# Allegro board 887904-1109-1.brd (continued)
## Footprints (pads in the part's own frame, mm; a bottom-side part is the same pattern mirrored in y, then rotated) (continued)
PG_VG93K_F_G2D112
  round 1.778 hole 0.711: 01(20.32,1.27) 02(17.78,-1.27) 03(15.24,1.27) 04(12.7,-1.27) 05(10.16,1.27) 06(7.62,-1.27) 07(5.08,1.27) 08(2.54,-1.27) 09(0,1.27) 10(-2.54,-1.27) 11(-5.08,1.27) 12(-7.62,-1.27) 13(-10.16,1.27) 14(-12.7,-1.27) 15(-15.24,1.27) 16(-17.78,-1.27) 17(-20.32,1.27)
  rect 1.778x1.778 hole 0.711: A1(20.32,3.81) A2(17.78,1.27) A3(15.24,3.81) A4(12.7,1.27) A5(10.16,3.81) A6(7.62,1.27) A7(5.08,3.81) A8(2.54,1.27) A9(0,3.81) A10(-2.54,1.27) A11(-5.08,3.81) A12(-7.62,1.27) A13(-10.16,3.81) A14(-12.7,1.27) A15(-15.24,3.81) A16(-17.78,1.27) A17(-20.32,3.81) B1(20.32,-1.27) B2(17.78,-3.81) B3(15.24,-1.27) B4(12.7,-3.81) B5(10.16,-1.27) B6(7.62,-3.81) B7(5.08,-1.27) B8(2.54,-3.81) B9(0,-1.27) B10(-2.54,-3.81) B11(-5.08,-1.27) B12(-7.62,-3.81) B13(-10.16,-1.27) B14(-12.7,-3.81) B15(-15.24,-1.27) B16(-17.78,-3.81) B17(-20.32,-1.27)
PG_VG93K_F_G2D113
  round 1.778 hole 0.711: 01(20.32,1.27) 02(17.78,-1.27) 03(15.24,1.27) 04(12.7,-1.27) 05(10.16,1.27) 06(7.62,-1.27) 07(5.08,1.27) 08(2.54,-1.27) 09(0,1.27) 10(-2.54,-1.27) 11(-5.08,1.27) 12(-7.62,-1.27) 13(-10.16,1.27) 14(-12.7,-1.27) 15(-15.24,1.27) 16(-17.78,-1.27) 17(-20.32,1.27)
  rect 1.778x1.778 hole 0.711: A1(20.32,3.81) A2(17.78,1.27) A3(15.24,3.81) A4(12.7,1.27) A5(10.16,3.81) A6(7.62,1.27) A7(5.08,3.81) A8(2.54,1.27) A9(0,3.81) A10(-2.54,1.27) A11(-5.08,3.81) A12(-7.62,1.27) A13(-10.16,3.81) A14(-12.7,1.27) A15(-15.24,3.81) A16(-17.78,1.27) A17(-20.32,3.81) B1(20.32,-1.27) B2(17.78,-3.81) B3(15.24,-1.27) B4(12.7,-3.81) B5(10.16,-1.27) B6(7.62,-3.81) B7(5.08,-1.27) B8(2.54,-3.81) B9(0,-1.27) B10(-2.54,-3.81) B11(-5.08,-1.27) B12(-7.62,-3.81) B13(-10.16,-1.27) B14(-12.7,-3.81) B15(-15.24,-1.27) B16(-17.78,-3.81) B17(-20.32,-1.27)
PG_VG93K_F_G2D114
  round 1.778 hole 0.711: 01(20.32,1.27) 02(17.78,-1.27) 03(15.24,1.27) 04(12.7,-1.27) 05(10.16,1.27) 06(7.62,-1.27) 07(5.08,1.27) 08(2.54,-1.27) 09(0,1.27) 10(-2.54,-1.27) 11(-5.08,1.27) 12(-7.62,-1.27) 13(-10.16,1.27) 14(-12.7,-1.27) 15(-15.24,1.27) 16(-17.78,-1.27) 17(-20.32,1.27)
  rect 1.778x1.778 hole 0.711: A1(20.32,3.81) A2(17.78,1.27) A3(15.24,3.81) A4(12.7,1.27) A5(10.16,3.81) A6(7.62,1.27) A7(5.08,3.81) A8(2.54,1.27) A9(0,3.81) A10(-2.54,1.27) A11(-5.08,3.81) A12(-7.62,1.27) A13(-10.16,3.81) A14(-12.7,1.27) A15(-15.24,3.81) A16(-17.78,1.27) A17(-20.32,3.81) B1(20.32,-1.27) B2(17.78,-3.81) B3(15.24,-1.27) B4(12.7,-3.81) B5(10.16,-1.27) B6(7.62,-3.81) B7(5.08,-1.27) B8(2.54,-3.81) B9(0,-1.27) B10(-2.54,-3.81) B11(-5.08,-1.27) B12(-7.62,-3.81) B13(-10.16,-1.27) B14(-12.7,-3.81) B15(-15.24,-1.27) B16(-17.78,-3.81) B17(-20.32,-1.27)
PG_VG93K_F_G2D115
  round 1.778 hole 0.711: 01(20.32,1.27) 02(17.78,-1.27) 03(15.24,1.27) 04(12.7,-1.27) 05(10.16,1.27) 06(7.62,-1.27) 07(5.08,1.27) 08(2.54,-1.27) 09(0,1.27) 10(-2.54,-1.27) 11(-5.08,1.27) 12(-7.62,-1.27) 13(-10.16,1.27) 14(-12.7,-1.27) 15(-15.24,1.27) 16(-17.78,-1.27) 17(-20.32,1.27)
  rect 1.778x1.778 hole 0.711: A1(20.32,3.81) A2(17.78,1.27) A3(15.24,3.81) A4(12.7,1.27) A5(10.16,3.81) A6(7.62,1.27) A7(5.08,3.81) A8(2.54,1.27) A9(0,3.81) A10(-2.54,1.27) A11(-5.08,3.81) A12(-7.62,1.27) A13(-10.16,3.81) A14(-12.7,1.27) A15(-15.24,3.81) A16(-17.78,1.27) A17(-20.32,3.81) B1(20.32,-1.27) B2(17.78,-3.81) B3(15.24,-1.27) B4(12.7,-3.81) B5(10.16,-1.27) B6(7.62,-3.81) B7(5.08,-1.27) B8(2.54,-3.81) B9(0,-1.27) B10(-2.54,-3.81) B11(-5.08,-1.27) B12(-7.62,-3.81) B13(-10.16,-1.27) B14(-12.7,-3.81) B15(-15.24,-1.27) B16(-17.78,-3.81) B17(-20.32,-1.27)
PG_VG93K_F_G2D116
  round 1.778 hole 0.711: 01(20.32,1.27) 02(17.78,-1.27) 03(15.24,1.27) 04(12.7,-1.27) 05(10.16,1.27) 06(7.62,-1.27) 07(5.08,1.27) 08(2.54,-1.27) 09(0,1.27) 10(-2.54,-1.27) 11(-5.08,1.27) 12(-7.62,-1.27) 13(-10.16,1.27) 14(-12.7,-1.27) 15(-15.24,1.27) 16(-17.78,-1.27) 17(-20.32,1.27)
  rect 1.778x1.778 hole 0.711: A1(20.32,3.81) A2(17.78,1.27) A3(15.24,3.81) A4(12.7,1.27) A5(10.16,3.81) A6(7.62,1.27) A7(5.08,3.81) A8(2.54,1.27) A9(0,3.81) A10(-2.54,1.27) A11(-5.08,3.81) A12(-7.62,1.27) A13(-10.16,3.81) A14(-12.7,1.27) A15(-15.24,3.81) A16(-17.78,1.27) A17(-20.32,3.81) B1(20.32,-1.27) B2(17.78,-3.81) B3(15.24,-1.27) B4(12.7,-3.81) B5(10.16,-1.27) B6(7.62,-3.81) B7(5.08,-1.27) B8(2.54,-3.81) B9(0,-1.27) B10(-2.54,-3.81) B11(-5.08,-1.27) B12(-7.62,-3.81) B13(-10.16,-1.27) B14(-12.7,-3.81) B15(-15.24,-1.27) B16(-17.78,-3.81) B17(-20.32,-1.27)
PG_VG93K_F_G2DPS2
  round 1.778 hole 0.711: A01(20.32,2.54) A02(17.78,2.54) A03(15.24,2.54) A04(12.7,2.54) A05(10.16,2.54) A06(7.62,2.54) A07(5.08,2.54) A08(2.54,2.54) A09(0,2.54) A10(-2.54,2.54) A11(-5.08,2.54) A12(-7.62,2.54) A13(-10.16,2.54) A14(-12.7,2.54) A15(-15.24,2.54) A16(-17.78,2.54) A17(-20.32,2.54) B01(20.32,0) B02(17.78,0) B03(15.24,0) B04(12.7,0) B05(10.16,0) B06(7.62,0) B07(5.08,0) B08(2.54,0) B09(0,0) B10(-2.54,0) B11(-5.08,0) B12(-7.62,0) B13(-10.16,0) B14(-12.7,0) B15(-15.24,0) B16(-17.78,0) B17(-20.32,0) C01(20.32,-2.54) C02(17.78,-2.54) C03(15.24,-2.54) C04(12.7,-2.54) C05(10.16,-2.54) C06(7.62,-2.54) C07(5.08,-2.54) C08(2.54,-2.54) C09(0,-2.54) C10(-2.54,-2.54) C11(-5.08,-2.54) C12(-7.62,-2.54) C13(-10.16,-2.54) C14(-12.7,-2.54) C15(-15.24,-2.54) C16(-17.78,-2.54) C17(-20.32,-2.54)
PG_VG93K_F_G2UTI3
  round 1.778 hole 0.711: A01(20.32,1.27) A02(17.78,1.27) A03(15.24,1.27) A04(12.7,1.27) A05(10.16,1.27) A06(7.62,1.27) A07(5.08,1.27) A08(2.54,1.27) A09(0,1.27) A10(-2.54,1.27) A11(-5.08,1.27) A12(-7.62,1.27) A13(-10.16,1.27) A14(-12.7,1.27) A15(-15.24,1.27) A16(-17.78,1.27) A17(-20.32,1.27) B01(20.32,-1.27) B02(17.78,-1.27) B03(15.24,-1.27) B04(12.7,-1.27) B05(10.16,-1.27) B06(7.62,-1.27) B07(5.08,-1.27) B08(2.54,-1.27) B09(0,-1.27) B10(-2.54,-1.27) B11(-5.08,-1.27) B12(-7.62,-1.27) B13(-10.16,-1.27) B14(-12.7,-1.27) B15(-15.24,-1.27) B16(-17.78,-1.27) B17(-20.32,-1.27)
PG_VG93K_F_G3D120
  round 1.778 hole 0.711: 01(-20.32,-1.27) 02(-17.78,1.27) 03(-15.24,-1.27) 04(-12.7,1.27) 05(-10.16,-1.27) 06(-7.62,1.27) 07(-5.08,-1.27) 08(-2.54,1.27) 09(0,-1.27) 10(2.54,1.27) 11(5.08,-1.27) 12(7.62,1.27) 13(10.16,-1.27) 14(12.7,1.27) 15(15.24,-1.27) 16(17.78,1.27) 17(20.32,-1.27)
  rect 1.778x1.778 hole 0.711: A1(-20.32,-3.81) A2(-17.78,-1.27) A3(-15.24,-3.81) A4(-12.7,-1.27) A5(-10.16,-3.81) A6(-7.62,-1.27) A7(-5.08,-3.81) A8(-2.54,-1.27) A9(0,-3.81) A10(2.54,-1.27) A11(5.08,-3.81) A12(7.62,-1.27) A13(10.16,-3.81) A14(12.7,-1.27) A15(15.24,-3.81) A16(17.78,-1.27) A17(20.32,-3.81) B1(-20.32,1.27) B2(-17.78,3.81) B3(-15.24,1.27) B4(-12.7,3.81) B5(-10.16,1.27) B6(-7.62,3.81) B7(-5.08,1.27) B8(-2.54,3.81) B9(0,1.27) B10(2.54,3.81) B11(5.08,1.27) B12(7.62,3.81) B13(10.16,1.27) B14(12.7,3.81) B15(15.24,1.27) B16(17.78,3.81) B17(20.32,1.27)
PG_VG93K_F_G3D124
  round 1.778 hole 0.711: 01(-20.32,-1.27) 02(-17.78,1.27) 03(-15.24,-1.27) 04(-12.7,1.27) 05(-10.16,-1.27) 06(-7.62,1.27) 07(-5.08,-1.27) 08(-2.54,1.27) 09(0,-1.27) 10(2.54,1.27) 11(5.08,-1.27) 12(7.62,1.27) 13(10.16,-1.27) 14(12.7,1.27) 15(15.24,-1.27) 16(17.78,1.27) 17(20.32,-1.27)
  rect 1.778x1.778 hole 0.711: A1(-20.32,-3.81) A2(-17.78,-1.27) A3(-15.24,-3.81) A4(-12.7,-1.27) A5(-10.16,-3.81) A6(-7.62,-1.27) A7(-5.08,-3.81) A8(-2.54,-1.27) A9(0,-3.81) A10(2.54,-1.27) A11(5.08,-3.81) A12(7.62,-1.27) A13(10.16,-3.81) A14(12.7,-1.27) A15(15.24,-3.81) A16(17.78,-1.27) A17(20.32,-3.81) B1(-20.32,1.27) B2(-17.78,3.81) B3(-15.24,1.27) B4(-12.7,3.81) B5(-10.16,1.27) B6(-7.62,3.81) B7(-5.08,1.27) B8(-2.54,3.81) B9(0,1.27) B10(2.54,3.81) B11(5.08,1.27) B12(7.62,3.81) B13(10.16,1.27) B14(12.7,3.81) B15(15.24,1.27) B16(17.78,3.81) B17(20.32,1.27)
PG_VG93K_F_G3D317
  round 1.778 hole 0.711: 01(-20.32,-1.27) 02(-17.78,1.27) 03(-15.24,-1.27) 04(-12.7,1.27) 05(-10.16,-1.27) 06(-7.62,1.27) 07(-5.08,-1.27) 08(-2.54,1.27) 09(0,-1.27) 10(2.54,1.27) 11(5.08,-1.27) 12(7.62,1.27) 13(10.16,-1.27) 14(12.7,1.27) 15(15.24,-1.27) 16(17.78,1.27) 17(20.32,-1.27)
  rect 1.778x1.778 hole 0.711: A1(-20.32,-3.81) A2(-17.78,-1.27) A3(-15.24,-3.81) A4(-12.7,-1.27) A5(-10.16,-3.81) A6(-7.62,-1.27) A7(-5.08,-3.81) A8(-2.54,-1.27) A9(0,-3.81) A10(2.54,-1.27) A11(5.08,-3.81) A12(7.62,-1.27) A13(10.16,-3.81) A14(12.7,-1.27) A15(15.24,-3.81) A16(17.78,-1.27) A17(20.32,-3.81) B1(-20.32,1.27) B2(-17.78,3.81) B3(-15.24,1.27) B4(-12.7,3.81) B5(-10.16,1.27) B6(-7.62,3.81) B7(-5.08,1.27) B8(-2.54,3.81) B9(0,1.27) B10(2.54,3.81) B11(5.08,1.27) B12(7.62,3.81) B13(10.16,1.27) B14(12.7,3.81) B15(15.24,1.27) B16(17.78,3.81) B17(20.32,1.27)
PG_VG93K_F_G3D318
  round 1.778 hole 0.711: 01(-20.32,-1.27) 02(-17.78,1.27) 03(-15.24,-1.27) 04(-12.7,1.27) 05(-10.16,-1.27) 06(-7.62,1.27) 07(-5.08,-1.27) 08(-2.54,1.27) 09(0,-1.27) 10(2.54,1.27) 11(5.08,-1.27) 12(7.62,1.27) 13(10.16,-1.27) 14(12.7,1.27) 15(15.24,-1.27) 16(17.78,1.27) 17(20.32,-1.27)
  rect 1.778x1.778 hole 0.711: A1(-20.32,-3.81) A2(-17.78,-1.27) A3(-15.24,-3.81) A4(-12.7,-1.27) A5(-10.16,-3.81) A6(-7.62,-1.27) A7(-5.08,-3.81) A8(-2.54,-1.27) A9(0,-3.81) A10(2.54,-1.27) A11(5.08,-3.81) A12(7.62,-1.27) A13(10.16,-3.81) A14(12.7,-1.27) A15(15.24,-3.81) A16(17.78,-1.27) A17(20.32,-3.81) B1(-20.32,1.27) B2(-17.78,3.81) B3(-15.24,1.27) B4(-12.7,3.81) B5(-10.16,1.27) B6(-7.62,3.81) B7(-5.08,1.27) B8(-2.54,3.81) B9(0,1.27) B10(2.54,3.81) B11(5.08,1.27) B12(7.62,3.81) B13(10.16,1.27) B14(12.7,3.81) B15(15.24,1.27) B16(17.78,3.81) B17(20.32,1.27)
PG_VG93K_F_G3D321
  round 1.778 hole 0.711: 01(-20.32,-1.27) 02(-17.78,1.27) 03(-15.24,-1.27) 04(-12.7,1.27) 05(-10.16,-1.27) 06(-7.62,1.27) 07(-5.08,-1.27) 08(-2.54,1.27) 09(0,-1.27) 10(2.54,1.27) 11(5.08,-1.27) 12(7.62,1.27) 13(10.16,-1.27) 14(12.7,1.27) 15(15.24,-1.27) 16(17.78,1.27) 17(20.32,-1.27)
  rect 1.778x1.778 hole 0.711: A1(-20.32,-3.81) A2(-17.78,-1.27) A3(-15.24,-3.81) A4(-12.7,-1.27) A5(-10.16,-3.81) A6(-7.62,-1.27) A7(-5.08,-3.81) A8(-2.54,-1.27) A9(0,-3.81) A10(2.54,-1.27) A11(5.08,-3.81) A12(7.62,-1.27) A13(10.16,-3.81) A14(12.7,-1.27) A15(15.24,-3.81) A16(17.78,-1.27) A17(20.32,-3.81) B1(-20.32,1.27) B2(-17.78,3.81) B3(-15.24,1.27) B4(-12.7,3.81) B5(-10.16,1.27) B6(-7.62,3.81) B7(-5.08,1.27) B8(-2.54,3.81) B9(0,1.27) B10(2.54,3.81) B11(5.08,1.27) B12(7.62,3.81) B13(10.16,1.27) B14(12.7,3.81) B15(15.24,1.27) B16(17.78,3.81) B17(20.32,1.27)
PG_VG93K_F_G3D322
  round 1.778 hole 0.711: 01(-20.32,-1.27) 02(-17.78,1.27) 03(-15.24,-1.27) 04(-12.7,1.27) 05(-10.16,-1.27) 06(-7.62,1.27) 07(-5.08,-1.27) 08(-2.54,1.27) 09(0,-1.27) 10(2.54,1.27) 11(5.08,-1.27) 12(7.62,1.27) 13(10.16,-1.27) 14(12.7,1.27) 15(15.24,-1.27) 16(17.78,1.27) 17(20.32,-1.27)
  rect 1.778x1.778 hole 0.711: A1(-20.32,-3.81) A2(-17.78,-1.27) A3(-15.24,-3.81) A4(-12.7,-1.27) A5(-10.16,-3.81) A6(-7.62,-1.27) A7(-5.08,-3.81) A8(-2.54,-1.27) A9(0,-3.81) A10(2.54,-1.27) A11(5.08,-3.81) A12(7.62,-1.27) A13(10.16,-3.81) A14(12.7,-1.27) A15(15.24,-3.81) A16(17.78,-1.27) A17(20.32,-3.81) B1(-20.32,1.27) B2(-17.78,3.81) B3(-15.24,1.27) B4(-12.7,3.81) B5(-10.16,1.27) B6(-7.62,3.81) B7(-5.08,1.27) B8(-2.54,3.81) B9(0,1.27) B10(2.54,3.81) B11(5.08,1.27) B12(7.62,3.81) B13(10.16,1.27) B14(12.7,3.81) B15(15.24,1.27) B16(17.78,3.81) B17(20.32,1.27)
PG_VG93K_F_G3DPS3
  round 1.778 hole 0.711: A01(-20.32,-2.54) A02(-17.78,-2.54) A03(-15.24,-2.54) A04(-12.7,-2.54) A05(-10.16,-2.54) A06(-7.62,-2.54) A07(-5.08,-2.54) A08(-2.54,-2.54) A09(0,-2.54) A10(2.54,-2.54) A11(5.08,-2.54) A12(7.62,-2.54) A13(10.16,-2.54) A14(12.7,-2.54) A15(15.24,-2.54) A16(17.78,-2.54) A17(20.32,-2.54) B01(-20.32,0) B02(-17.78,0) B03(-15.24,0) B04(-12.7,0) B05(-10.16,0) B06(-7.62,0) B07(-5.08,0) B08(-2.54,0) B09(0,0) B10(2.54,0) B11(5.08,0) B12(7.62,0) B13(10.16,0) B14(12.7,0) B15(15.24,0) B16(17.78,0) B17(20.32,0) C01(-20.32,2.54) C02(-17.78,2.54) C03(-15.24,2.54) C04(-12.7,2.54) C05(-10.16,2.54) C06(-7.62,2.54) C07(-5.08,2.54) C08(-2.54,2.54) C09(0,2.54) C10(2.54,2.54) C11(5.08,2.54) C12(7.62,2.54) C13(10.16,2.54) C14(12.7,2.54) C15(15.24,2.54) C16(17.78,2.54) C17(20.32,2.54)
PG_VG93K_F_G3UTI1
  round 1.778 hole 0.711: A01(-20.32,-1.27) A02(-17.78,-1.27) A03(-15.24,-1.27) A04(-12.7,-1.27) A05(-10.16,-1.27) A06(-7.62,-1.27) A07(-5.08,-1.27) A08(-2.54,-1.27) A09(0,-1.27) A10(2.54,-1.27) A11(5.08,-1.27) A12(7.62,-1.27) A13(10.16,-1.27) A14(12.7,-1.27) A15(15.24,-1.27) A16(17.78,-1.27) A17(20.32,-1.27) B01(-20.32,1.27) B02(-17.78,1.27) B03(-15.24,1.27) B04(-12.7,1.27) B05(-10.16,1.27) B06(-7.62,1.27) B07(-5.08,1.27) B08(-2.54,1.27) B09(0,1.27) B10(2.54,1.27) B11(5.08,1.27) B12(7.62,1.27) B13(10.16,1.27) B14(12.7,1.27) B15(15.24,1.27) B16(17.78,1.27) B17(20.32,1.27)
PG_VG93K_F_G4D125
  round 1.778 hole 0.711: 01(-20.32,-1.27) 02(-17.78,1.27) 03(-15.24,-1.27) 04(-12.7,1.27) 05(-10.16,-1.27) 06(-7.62,1.27) 07(-5.08,-1.27) 08(-2.54,1.27) 09(0,-1.27) 10(2.54,1.27) 11(5.08,-1.27) 12(7.62,1.27) 13(10.16,-1.27) 14(12.7,1.27) 15(15.24,-1.27) 16(17.78,1.27) 17(20.32,-1.27)
  rect 1.778x1.778 hole 0.711: A1(-20.32,-3.81) A2(-17.78,-1.27) A3(-15.24,-3.81) A4(-12.7,-1.27) A5(-10.16,-3.81) A6(-7.62,-1.27) A7(-5.08,-3.81) A8(-2.54,-1.27) A9(0,-3.81) A10(2.54,-1.27) A11(5.08,-3.81) A12(7.62,-1.27) A13(10.16,-3.81) A14(12.7,-1.27) A15(15.24,-3.81) A16(17.78,-1.27) A17(20.32,-3.81) B1(-20.32,1.27) B2(-17.78,3.81) B3(-15.24,1.27) B4(-12.7,3.81) B5(-10.16,1.27) B6(-7.62,3.81) B7(-5.08,1.27) B8(-2.54,3.81) B9(0,1.27) B10(2.54,3.81) B11(5.08,1.27) B12(7.62,3.81) B13(10.16,1.27) B14(12.7,3.81) B15(15.24,1.27) B16(17.78,3.81) B17(20.32,1.27)
PG_VG93K_F_G4D126
  round 1.778 hole 0.711: 01(-20.32,-1.27) 02(-17.78,1.27) 03(-15.24,-1.27) 04(-12.7,1.27) 05(-10.16,-1.27) 06(-7.62,1.27) 07(-5.08,-1.27) 08(-2.54,1.27) 09(0,-1.27) 10(2.54,1.27) 11(5.08,-1.27) 12(7.62,1.27) 13(10.16,-1.27) 14(12.7,1.27) 15(15.24,-1.27) 16(17.78,1.27) 17(20.32,-1.27)
  rect 1.778x1.778 hole 0.711: A1(-20.32,-3.81) A2(-17.78,-1.27) A3(-15.24,-3.81) A4(-12.7,-1.27) A5(-10.16,-3.81) A6(-7.62,-1.27) A7(-5.08,-3.81) A8(-2.54,-1.27) A9(0,-3.81) A10(2.54,-1.27) A11(5.08,-3.81) A12(7.62,-1.27) A13(10.16,-3.81) A14(12.7,-1.27) A15(15.24,-3.81) A16(17.78,-1.27) A17(20.32,-3.81) B1(-20.32,1.27) B2(-17.78,3.81) B3(-15.24,1.27) B4(-12.7,3.81) B5(-10.16,1.27) B6(-7.62,3.81) B7(-5.08,1.27) B8(-2.54,3.81) B9(0,1.27) B10(2.54,3.81) B11(5.08,1.27) B12(7.62,3.81) B13(10.16,1.27) B14(12.7,3.81) B15(15.24,1.27) B16(17.78,3.81) B17(20.32,1.27)
PG_VG93K_F_G4D127
  round 1.778 hole 0.711: 01(-20.32,-1.27) 02(-17.78,1.27) 03(-15.24,-1.27) 04(-12.7,1.27) 05(-10.16,-1.27) 06(-7.62,1.27) 07(-5.08,-1.27) 08(-2.54,1.27) 09(0,-1.27) 10(2.54,1.27) 11(5.08,-1.27) 12(7.62,1.27) 13(10.16,-1.27) 14(12.7,1.27) 15(15.24,-1.27) 16(17.78,1.27) 17(20.32,-1.27)
  rect 1.778x1.778 hole 0.711: A1(-20.32,-3.81) A2(-17.78,-1.27) A3(-15.24,-3.81) A4(-12.7,-1.27) A5(-10.16,-3.81) A6(-7.62,-1.27) A7(-5.08,-3.81) A8(-2.54,-1.27) A9(0,-3.81) A10(2.54,-1.27) A11(5.08,-3.81) A12(7.62,-1.27) A13(10.16,-3.81) A14(12.7,-1.27) A15(15.24,-3.81) A16(17.78,-1.27) A17(20.32,-3.81) B1(-20.32,1.27) B2(-17.78,3.81) B3(-15.24,1.27) B4(-12.7,3.81) B5(-10.16,1.27) B6(-7.62,3.81) B7(-5.08,1.27) B8(-2.54,3.81) B9(0,1.27) B10(2.54,3.81) B11(5.08,1.27) B12(7.62,3.81) B13(10.16,1.27) B14(12.7,3.81) B15(15.24,1.27) B16(17.78,3.81) B17(20.32,1.27)
PG_VG93K_F_G4D128
  round 1.778 hole 0.711: 01(-20.32,-1.27) 02(-17.78,1.27) 03(-15.24,-1.27) 04(-12.7,1.27) 05(-10.16,-1.27) 06(-7.62,1.27) 07(-5.08,-1.27) 08(-2.54,1.27) 09(0,-1.27) 10(2.54,1.27) 11(5.08,-1.27) 12(7.62,1.27) 13(10.16,-1.27) 14(12.7,1.27) 15(15.24,-1.27) 16(17.78,1.27) 17(20.32,-1.27)
  rect 1.778x1.778 hole 0.711: A1(-20.32,-3.81) A2(-17.78,-1.27) A3(-15.24,-3.81) A4(-12.7,-1.27) A5(-10.16,-3.81) A6(-7.62,-1.27) A7(-5.08,-3.81) A8(-2.54,-1.27) A9(0,-3.81) A10(2.54,-1.27) A11(5.08,-3.81) A12(7.62,-1.27) A13(10.16,-3.81) A14(12.7,-1.27) A15(15.24,-3.81) A16(17.78,-1.27) A17(20.32,-3.81) B1(-20.32,1.27) B2(-17.78,3.81) B3(-15.24,1.27) B4(-12.7,3.81) B5(-10.16,1.27) B6(-7.62,3.81) B7(-5.08,1.27) B8(-2.54,3.81) B9(0,1.27) B10(2.54,3.81) B11(5.08,1.27) B12(7.62,3.81) B13(10.16,1.27) B14(12.7,3.81) B15(15.24,1.27) B16(17.78,3.81) B17(20.32,1.27)
PG_VG93K_F_G4D129
  round 1.778 hole 0.711: 01(-20.32,-1.27) 02(-17.78,1.27) 03(-15.24,-1.27) 04(-12.7,1.27) 05(-10.16,-1.27) 06(-7.62,1.27) 07(-5.08,-1.27) 08(-2.54,1.27) 09(0,-1.27) 10(2.54,1.27) 11(5.08,-1.27) 12(7.62,1.27) 13(10.16,-1.27) 14(12.7,1.27) 15(15.24,-1.27) 16(17.78,1.27) 17(20.32,-1.27)
  rect 1.778x1.778 hole 0.711: A1(-20.32,-3.81) A2(-17.78,-1.27) A3(-15.24,-3.81) A4(-12.7,-1.27) A5(-10.16,-3.81) A6(-7.62,-1.27) A7(-5.08,-3.81) A8(-2.54,-1.27) A9(0,-3.81) A10(2.54,-1.27) A11(5.08,-3.81) A12(7.62,-1.27) A13(10.16,-3.81) A14(12.7,-1.27) A15(15.24,-3.81) A16(17.78,-1.27) A17(20.32,-3.81) B1(-20.32,1.27) B2(-17.78,3.81) B3(-15.24,1.27) B4(-12.7,3.81) B5(-10.16,1.27) B6(-7.62,3.81) B7(-5.08,1.27) B8(-2.54,3.81) B9(0,1.27) B10(2.54,3.81) B11(5.08,1.27) B12(7.62,3.81) B13(10.16,1.27) B14(12.7,3.81) B15(15.24,1.27) B16(17.78,3.81) B17(20.32,1.27)
PG_VG93K_F_G4D130
  round 1.778 hole 0.711: 01(-20.32,-1.27) 02(-17.78,1.27) 03(-15.24,-1.27) 04(-12.7,1.27) 05(-10.16,-1.27) 06(-7.62,1.27) 07(-5.08,-1.27) 08(-2.54,1.27) 09(0,-1.27) 10(2.54,1.27) 11(5.08,-1.27) 12(7.62,1.27) 13(10.16,-1.27) 14(12.7,1.27) 15(15.24,-1.27) 16(17.78,1.27) 17(20.32,-1.27)
  rect 1.778x1.778 hole 0.711: A1(-20.32,-3.81) A2(-17.78,-1.27) A3(-15.24,-3.81) A4(-12.7,-1.27) A5(-10.16,-3.81) A6(-7.62,-1.27) A7(-5.08,-3.81) A8(-2.54,-1.27) A9(0,-3.81) A10(2.54,-1.27) A11(5.08,-3.81) A12(7.62,-1.27) A13(10.16,-3.81) A14(12.7,-1.27) A15(15.24,-3.81) A16(17.78,-1.27) A17(20.32,-3.81) B1(-20.32,1.27) B2(-17.78,3.81) B3(-15.24,1.27) B4(-12.7,3.81) B5(-10.16,1.27) B6(-7.62,3.81) B7(-5.08,1.27) B8(-2.54,3.81) B9(0,1.27) B10(2.54,3.81) B11(5.08,1.27) B12(7.62,3.81) B13(10.16,1.27) B14(12.7,3.81) B15(15.24,1.27) B16(17.78,3.81) B17(20.32,1.27)
PG_VG93K_F_G4D131
  round 1.778 hole 0.711: 01(-20.32,-1.27) 02(-17.78,1.27) 03(-15.24,-1.27) 04(-12.7,1.27) 05(-10.16,-1.27) 06(-7.62,1.27) 07(-5.08,-1.27) 08(-2.54,1.27) 09(0,-1.27) 10(2.54,1.27) 11(5.08,-1.27) 12(7.62,1.27) 13(10.16,-1.27) 14(12.7,1.27) 15(15.24,-1.27) 16(17.78,1.27) 17(20.32,-1.27)
  rect 1.778x1.778 hole 0.711: A1(-20.32,-3.81) A2(-17.78,-1.27) A3(-15.24,-3.81) A4(-12.7,-1.27) A5(-10.16,-3.81) A6(-7.62,-1.27) A7(-5.08,-3.81) A8(-2.54,-1.27) A9(0,-3.81) A10(2.54,-1.27) A11(5.08,-3.81) A12(7.62,-1.27) A13(10.16,-3.81) A14(12.7,-1.27) A15(15.24,-3.81) A16(17.78,-1.27) A17(20.32,-3.81) B1(-20.32,1.27) B2(-17.78,3.81) B3(-15.24,1.27) B4(-12.7,3.81) B5(-10.16,1.27) B6(-7.62,3.81) B7(-5.08,1.27) B8(-2.54,3.81) B9(0,1.27) B10(2.54,3.81) B11(5.08,1.27) B12(7.62,3.81) B13(10.16,1.27) B14(12.7,3.81) B15(15.24,1.27) B16(17.78,3.81) B17(20.32,1.27)
PG_VG93K_F_G4D132
  round 1.778 hole 0.711: 01(-20.32,-1.27) 02(-17.78,1.27) 03(-15.24,-1.27) 04(-12.7,1.27) 05(-10.16,-1.27) 06(-7.62,1.27) 07(-5.08,-1.27) 08(-2.54,1.27) 09(0,-1.27) 10(2.54,1.27) 11(5.08,-1.27) 12(7.62,1.27) 13(10.16,-1.27) 14(12.7,1.27) 15(15.24,-1.27) 16(17.78,1.27) 17(20.32,-1.27)
  rect 1.778x1.778 hole 0.711: A1(-20.32,-3.81) A2(-17.78,-1.27) A3(-15.24,-3.81) A4(-12.7,-1.27) A5(-10.16,-3.81) A6(-7.62,-1.27) A7(-5.08,-3.81) A8(-2.54,-1.27) A9(0,-3.81) A10(2.54,-1.27) A11(5.08,-3.81) A12(7.62,-1.27) A13(10.16,-3.81) A14(12.7,-1.27) A15(15.24,-3.81) A16(17.78,-1.27) A17(20.32,-3.81) B1(-20.32,1.27) B2(-17.78,3.81) B3(-15.24,1.27) B4(-12.7,3.81) B5(-10.16,1.27) B6(-7.62,3.81) B7(-5.08,1.27) B8(-2.54,3.81) B9(0,1.27) B10(2.54,3.81) B11(5.08,1.27) B12(7.62,3.81) B13(10.16,1.27) B14(12.7,3.81) B15(15.24,1.27) B16(17.78,3.81) B17(20.32,1.27)
PG_VG93K_F_G4DPS4
  round 1.778 hole 0.711: A01(-20.32,-2.54) A02(-17.78,-2.54) A03(-15.24,-2.54) A04(-12.7,-2.54) A05(-10.16,-2.54) A06(-7.62,-2.54) A07(-5.08,-2.54) A08(-2.54,-2.54) A09(0,-2.54) A10(2.54,-2.54) A11(5.08,-2.54) A12(7.62,-2.54) A13(10.16,-2.54) A14(12.7,-2.54) A15(15.24,-2.54) A16(17.78,-2.54) A17(20.32,-2.54) B01(-20.32,0) B02(-17.78,0) B03(-15.24,0) B04(-12.7,0) B05(-10.16,0) B06(-7.62,0) B07(-5.08,0) B08(-2.54,0) B09(0,0) B10(2.54,0) B11(5.08,0) B12(7.62,0) B13(10.16,0) B14(12.7,0) B15(15.24,0) B16(17.78,0) B17(20.32,0) C01(-20.32,2.54) C02(-17.78,2.54) C03(-15.24,2.54) C04(-12.7,2.54) C05(-10.16,2.54) C06(-7.62,2.54) C07(-5.08,2.54) C08(-2.54,2.54) C09(0,2.54) C10(2.54,2.54) C11(5.08,2.54) C12(7.62,2.54) C13(10.16,2.54) C14(12.7,2.54) C15(15.24,2.54) C16(17.78,2.54) C17(20.32,2.54)
PG_VG93K_F_G4UTI5
  round 1.778 hole 0.711: A01(-20.32,-1.27) A02(-17.78,-1.27) A03(-15.24,-1.27) A04(-12.7,-1.27) A05(-10.16,-1.27) A06(-7.62,-1.27) A07(-5.08,-1.27) A08(-2.54,-1.27) A09(0,-1.27) A10(2.54,-1.27) A11(5.08,-1.27) A12(7.62,-1.27) A13(10.16,-1.27) A14(12.7,-1.27) A15(15.24,-1.27) A16(17.78,-1.27) A17(20.32,-1.27) B01(-20.32,1.27) B02(-17.78,1.27) B03(-15.24,1.27) B04(-12.7,1.27) B05(-10.16,1.27) B06(-7.62,1.27) B07(-5.08,1.27) B08(-2.54,1.27) B09(0,1.27) B10(2.54,1.27) B11(5.08,1.27) B12(7.62,1.27) B13(10.16,1.27) B14(12.7,1.27) B15(15.24,1.27) B16(17.78,1.27) B17(20.32,1.27)
PG_VG93K_F_G5D201
  round 1.778 hole 0.711: 01(-20.32,-1.27) 02(-17.78,1.27) 03(-15.24,-1.27) 04(-12.7,1.27) 05(-10.16,-1.27) 06(-7.62,1.27) 07(-5.08,-1.27) 08(-2.54,1.27) 09(0,-1.27) 10(2.54,1.27) 11(5.08,-1.27) 12(7.62,1.27) 13(10.16,-1.27) 14(12.7,1.27) 15(15.24,-1.27) 16(17.78,1.27) 17(20.32,-1.27)
  rect 1.778x1.778 hole 0.711: A1(-20.32,-3.81) A2(-17.78,-1.27) A3(-15.24,-3.81) A4(-12.7,-1.27) A5(-10.16,-3.81) A6(-7.62,-1.27) A7(-5.08,-3.81) A8(-2.54,-1.27) A9(0,-3.81) A10(2.54,-1.27) A11(5.08,-3.81) A12(7.62,-1.27) A13(10.16,-3.81) A14(12.7,-1.27) A15(15.24,-3.81) A16(17.78,-1.27) A17(20.32,-3.81) B1(-20.32,1.27) B2(-17.78,3.81) B3(-15.24,1.27) B4(-12.7,3.81) B5(-10.16,1.27) B6(-7.62,3.81) B7(-5.08,1.27) B8(-2.54,3.81) B9(0,1.27) B10(2.54,3.81) B11(5.08,1.27) B12(7.62,3.81) B13(10.16,1.27) B14(12.7,3.81) B15(15.24,1.27) B16(17.78,3.81) B17(20.32,1.27)
PG_VG93K_F_G5D202
  round 1.778 hole 0.711: 01(-20.32,-1.27) 02(-17.78,1.27) 03(-15.24,-1.27) 04(-12.7,1.27) 05(-10.16,-1.27) 06(-7.62,1.27) 07(-5.08,-1.27) 08(-2.54,1.27) 09(0,-1.27) 10(2.54,1.27) 11(5.08,-1.27) 12(7.62,1.27) 13(10.16,-1.27) 14(12.7,1.27) 15(15.24,-1.27) 16(17.78,1.27) 17(20.32,-1.27)
  rect 1.778x1.778 hole 0.711: A1(-20.32,-3.81) A2(-17.78,-1.27) A3(-15.24,-3.81) A4(-12.7,-1.27) A5(-10.16,-3.81) A6(-7.62,-1.27) A7(-5.08,-3.81) A8(-2.54,-1.27) A9(0,-3.81) A10(2.54,-1.27) A11(5.08,-3.81) A12(7.62,-1.27) A13(10.16,-3.81) A14(12.7,-1.27) A15(15.24,-3.81) A16(17.78,-1.27) A17(20.32,-3.81) B1(-20.32,1.27) B2(-17.78,3.81) B3(-15.24,1.27) B4(-12.7,3.81) B5(-10.16,1.27) B6(-7.62,3.81) B7(-5.08,1.27) B8(-2.54,3.81) B9(0,1.27) B10(2.54,3.81) B11(5.08,1.27) B12(7.62,3.81) B13(10.16,1.27) B14(12.7,3.81) B15(15.24,1.27) B16(17.78,3.81) B17(20.32,1.27)
PG_VG93K_F_G5D203
  round 1.778 hole 0.711: 01(-20.32,-1.27) 02(-17.78,1.27) 03(-15.24,-1.27) 04(-12.7,1.27) 05(-10.16,-1.27) 06(-7.62,1.27) 07(-5.08,-1.27) 08(-2.54,1.27) 09(0,-1.27) 10(2.54,1.27) 11(5.08,-1.27) 12(7.62,1.27) 13(10.16,-1.27) 14(12.7,1.27) 15(15.24,-1.27) 16(17.78,1.27) 17(20.32,-1.27)
  rect 1.778x1.778 hole 0.711: A1(-20.32,-3.81) A2(-17.78,-1.27) A3(-15.24,-3.81) A4(-12.7,-1.27) A5(-10.16,-3.81) A6(-7.62,-1.27) A7(-5.08,-3.81) A8(-2.54,-1.27) A9(0,-3.81) A10(2.54,-1.27) A11(5.08,-3.81) A12(7.62,-1.27) A13(10.16,-3.81) A14(12.7,-1.27) A15(15.24,-3.81) A16(17.78,-1.27) A17(20.32,-3.81) B1(-20.32,1.27) B2(-17.78,3.81) B3(-15.24,1.27) B4(-12.7,3.81) B5(-10.16,1.27) B6(-7.62,3.81) B7(-5.08,1.27) B8(-2.54,3.81) B9(0,1.27) B10(2.54,3.81) B11(5.08,1.27) B12(7.62,3.81) B13(10.16,1.27) B14(12.7,3.81) B15(15.24,1.27) B16(17.78,3.81) B17(20.32,1.27)
PG_VG93K_F_G5D204
  round 1.778 hole 0.711: 01(-20.32,-1.27) 02(-17.78,1.27) 03(-15.24,-1.27) 04(-12.7,1.27) 05(-10.16,-1.27) 06(-7.62,1.27) 07(-5.08,-1.27) 08(-2.54,1.27) 09(0,-1.27) 10(2.54,1.27) 11(5.08,-1.27) 12(7.62,1.27) 13(10.16,-1.27) 14(12.7,1.27) 15(15.24,-1.27) 16(17.78,1.27) 17(20.32,-1.27)
  rect 1.778x1.778 hole 0.711: A1(-20.32,-3.81) A2(-17.78,-1.27) A3(-15.24,-3.81) A4(-12.7,-1.27) A5(-10.16,-3.81) A6(-7.62,-1.27) A7(-5.08,-3.81) A8(-2.54,-1.27) A9(0,-3.81) A10(2.54,-1.27) A11(5.08,-3.81) A12(7.62,-1.27) A13(10.16,-3.81) A14(12.7,-1.27) A15(15.24,-3.81) A16(17.78,-1.27) A17(20.32,-3.81) B1(-20.32,1.27) B2(-17.78,3.81) B3(-15.24,1.27) B4(-12.7,3.81) B5(-10.16,1.27) B6(-7.62,3.81) B7(-5.08,1.27) B8(-2.54,3.81) B9(0,1.27) B10(2.54,3.81) B11(5.08,1.27) B12(7.62,3.81) B13(10.16,1.27) B14(12.7,3.81) B15(15.24,1.27) B16(17.78,3.81) B17(20.32,1.27)
PG_VG93K_F_G5D205
  round 1.778 hole 0.711: 01(-20.32,-1.27) 02(-17.78,1.27) 03(-15.24,-1.27) 04(-12.7,1.27) 05(-10.16,-1.27) 06(-7.62,1.27) 07(-5.08,-1.27) 08(-2.54,1.27) 09(0,-1.27) 10(2.54,1.27) 11(5.08,-1.27) 12(7.62,1.27) 13(10.16,-1.27) 14(12.7,1.27) 15(15.24,-1.27) 16(17.78,1.27) 17(20.32,-1.27)
  rect 1.778x1.778 hole 0.711: A1(-20.32,-3.81) A2(-17.78,-1.27) A3(-15.24,-3.81) A4(-12.7,-1.27) A5(-10.16,-3.81) A6(-7.62,-1.27) A7(-5.08,-3.81) A8(-2.54,-1.27) A9(0,-3.81) A10(2.54,-1.27) A11(5.08,-3.81) A12(7.62,-1.27) A13(10.16,-3.81) A14(12.7,-1.27) A15(15.24,-3.81) A16(17.78,-1.27) A17(20.32,-3.81) B1(-20.32,1.27) B2(-17.78,3.81) B3(-15.24,1.27) B4(-12.7,3.81) B5(-10.16,1.27) B6(-7.62,3.81) B7(-5.08,1.27) B8(-2.54,3.81) B9(0,1.27) B10(2.54,3.81) B11(5.08,1.27) B12(7.62,3.81) B13(10.16,1.27) B14(12.7,3.81) B15(15.24,1.27) B16(17.78,3.81) B17(20.32,1.27)
PG_VG93K_F_G5D206
  round 1.778 hole 0.711: 01(-20.32,-1.27) 02(-17.78,1.27) 03(-15.24,-1.27) 04(-12.7,1.27) 05(-10.16,-1.27) 06(-7.62,1.27) 07(-5.08,-1.27) 08(-2.54,1.27) 09(0,-1.27) 10(2.54,1.27) 11(5.08,-1.27) 12(7.62,1.27) 13(10.16,-1.27) 14(12.7,1.27) 15(15.24,-1.27) 16(17.78,1.27) 17(20.32,-1.27)
  rect 1.778x1.778 hole 0.711: A1(-20.32,-3.81) A2(-17.78,-1.27) A3(-15.24,-3.81) A4(-12.7,-1.27) A5(-10.16,-3.81) A6(-7.62,-1.27) A7(-5.08,-3.81) A8(-2.54,-1.27) A9(0,-3.81) A10(2.54,-1.27) A11(5.08,-3.81) A12(7.62,-1.27) A13(10.16,-3.81) A14(12.7,-1.27) A15(15.24,-3.81) A16(17.78,-1.27) A17(20.32,-3.81) B1(-20.32,1.27) B2(-17.78,3.81) B3(-15.24,1.27) B4(-12.7,3.81) B5(-10.16,1.27) B6(-7.62,3.81) B7(-5.08,1.27) B8(-2.54,3.81) B9(0,1.27) B10(2.54,3.81) B11(5.08,1.27) B12(7.62,3.81) B13(10.16,1.27) B14(12.7,3.81) B15(15.24,1.27) B16(17.78,3.81) B17(20.32,1.27)
PG_VG93K_F_G5D207
  round 1.778 hole 0.711: 01(-20.32,-1.27) 02(-17.78,1.27) 03(-15.24,-1.27) 04(-12.7,1.27) 05(-10.16,-1.27) 06(-7.62,1.27) 07(-5.08,-1.27) 08(-2.54,1.27) 09(0,-1.27) 10(2.54,1.27) 11(5.08,-1.27) 12(7.62,1.27) 13(10.16,-1.27) 14(12.7,1.27) 15(15.24,-1.27) 16(17.78,1.27) 17(20.32,-1.27)
  rect 1.778x1.778 hole 0.711: A1(-20.32,-3.81) A2(-17.78,-1.27) A3(-15.24,-3.81) A4(-12.7,-1.27) A5(-10.16,-3.81) A6(-7.62,-1.27) A7(-5.08,-3.81) A8(-2.54,-1.27) A9(0,-3.81) A10(2.54,-1.27) A11(5.08,-3.81) A12(7.62,-1.27) A13(10.16,-3.81) A14(12.7,-1.27) A15(15.24,-3.81) A16(17.78,-1.27) A17(20.32,-3.81) B1(-20.32,1.27) B2(-17.78,3.81) B3(-15.24,1.27) B4(-12.7,3.81) B5(-10.16,1.27) B6(-7.62,3.81) B7(-5.08,1.27) B8(-2.54,3.81) B9(0,1.27) B10(2.54,3.81) B11(5.08,1.27) B12(7.62,3.81) B13(10.16,1.27) B14(12.7,3.81) B15(15.24,1.27) B16(17.78,3.81) B17(20.32,1.27)
PG_VG93K_F_G5D208
  round 1.778 hole 0.711: 01(-20.32,-1.27) 02(-17.78,1.27) 03(-15.24,-1.27) 04(-12.7,1.27) 05(-10.16,-1.27) 06(-7.62,1.27) 07(-5.08,-1.27) 08(-2.54,1.27) 09(0,-1.27) 10(2.54,1.27) 11(5.08,-1.27) 12(7.62,1.27) 13(10.16,-1.27) 14(12.7,1.27) 15(15.24,-1.27) 16(17.78,1.27) 17(20.32,-1.27)
  rect 1.778x1.778 hole 0.711: A1(-20.32,-3.81) A2(-17.78,-1.27) A3(-15.24,-3.81) A4(-12.7,-1.27) A5(-10.16,-3.81) A6(-7.62,-1.27) A7(-5.08,-3.81) A8(-2.54,-1.27) A9(0,-3.81) A10(2.54,-1.27) A11(5.08,-3.81) A12(7.62,-1.27) A13(10.16,-3.81) A14(12.7,-1.27) A15(15.24,-3.81) A16(17.78,-1.27) A17(20.32,-3.81) B1(-20.32,1.27) B2(-17.78,3.81) B3(-15.24,1.27) B4(-12.7,3.81) B5(-10.16,1.27) B6(-7.62,3.81) B7(-5.08,1.27) B8(-2.54,3.81) B9(0,1.27) B10(2.54,3.81) B11(5.08,1.27) B12(7.62,3.81) B13(10.16,1.27) B14(12.7,3.81) B15(15.24,1.27) B16(17.78,3.81) B17(20.32,1.27)
PG_VG93K_F_G5DPS5
  round 1.778 hole 0.711: A01(-20.32,-2.54) A02(-17.78,-2.54) A03(-15.24,-2.54) A04(-12.7,-2.54) A05(-10.16,-2.54) A06(-7.62,-2.54) A07(-5.08,-2.54) A08(-2.54,-2.54) A09(0,-2.54) A10(2.54,-2.54) A11(5.08,-2.54) A12(7.62,-2.54) A13(10.16,-2.54) A14(12.7,-2.54) A15(15.24,-2.54) A16(17.78,-2.54) A17(20.32,-2.54) B01(-20.32,0) B02(-17.78,0) B03(-15.24,0) B04(-12.7,0) B05(-10.16,0) B06(-7.62,0) B07(-5.08,0) B08(-2.54,0) B09(0,0) B10(2.54,0) B11(5.08,0) B12(7.62,0) B13(10.16,0) B14(12.7,0) B15(15.24,0) B16(17.78,0) B17(20.32,0) C01(-20.32,2.54) C02(-17.78,2.54) C03(-15.24,2.54) C04(-12.7,2.54) C05(-10.16,2.54) C06(-7.62,2.54) C07(-5.08,2.54) C08(-2.54,2.54) C09(0,2.54) C10(2.54,2.54) C11(5.08,2.54) C12(7.62,2.54) C13(10.16,2.54) C14(12.7,2.54) C15(15.24,2.54) C16(17.78,2.54) C17(20.32,2.54)
PG_VG93K_F_G5UTI6
  round 1.778 hole 0.711: A01(-20.32,-1.27) A02(-17.78,-1.27) A03(-15.24,-1.27) A04(-12.7,-1.27) A05(-10.16,-1.27) A06(-7.62,-1.27) A07(-5.08,-1.27) A08(-2.54,-1.27) A09(0,-1.27) A10(2.54,-1.27) A11(5.08,-1.27) A12(7.62,-1.27) A13(10.16,-1.27) A14(12.7,-1.27) A15(15.24,-1.27) A16(17.78,-1.27) A17(20.32,-1.27) B01(-20.32,1.27) B02(-17.78,1.27) B03(-15.24,1.27) B04(-12.7,1.27) B05(-10.16,1.27) B06(-7.62,1.27) B07(-5.08,1.27) B08(-2.54,1.27) B09(0,1.27) B10(2.54,1.27) B11(5.08,1.27) B12(7.62,1.27) B13(10.16,1.27) B14(12.7,1.27) B15(15.24,1.27) B16(17.78,1.27) B17(20.32,1.27)
PG_VG93K_F_G6D209
  round 1.778 hole 0.711: 01(20.32,1.27) 02(17.78,-1.27) 03(15.24,1.27) 04(12.7,-1.27) 05(10.16,1.27) 06(7.62,-1.27) 07(5.08,1.27) 08(2.54,-1.27) 09(0,1.27) 10(-2.54,-1.27) 11(-5.08,1.27) 12(-7.62,-1.27) 13(-10.16,1.27) 14(-12.7,-1.27) 15(-15.24,1.27) 16(-17.78,-1.27) 17(-20.32,1.27)
  rect 1.778x1.778 hole 0.711: A1(20.32,3.81) A2(17.78,1.27) A3(15.24,3.81) A4(12.7,1.27) A5(10.16,3.81) A6(7.62,1.27) A7(5.08,3.81) A8(2.54,1.27) A9(0,3.81) A10(-2.54,1.27) A11(-5.08,3.81) A12(-7.62,1.27) A13(-10.16,3.81) A14(-12.7,1.27) A15(-15.24,3.81) A16(-17.78,1.27) A17(-20.32,3.81) B1(20.32,-1.27) B2(17.78,-3.81) B3(15.24,-1.27) B4(12.7,-3.81) B5(10.16,-1.27) B6(7.62,-3.81) B7(5.08,-1.27) B8(2.54,-3.81) B9(0,-1.27) B10(-2.54,-3.81) B11(-5.08,-1.27) B12(-7.62,-3.81) B13(-10.16,-1.27) B14(-12.7,-3.81) B15(-15.24,-1.27) B16(-17.78,-3.81) B17(-20.32,-1.27)
PG_VG93K_F_G6D210
  round 1.778 hole 0.711: 01(20.32,1.27) 02(17.78,-1.27) 03(15.24,1.27) 04(12.7,-1.27) 05(10.16,1.27) 06(7.62,-1.27) 07(5.08,1.27) 08(2.54,-1.27) 09(0,1.27) 10(-2.54,-1.27) 11(-5.08,1.27) 12(-7.62,-1.27) 13(-10.16,1.27) 14(-12.7,-1.27) 15(-15.24,1.27) 16(-17.78,-1.27) 17(-20.32,1.27)
  rect 1.778x1.778 hole 0.711: A1(20.32,3.81) A2(17.78,1.27) A3(15.24,3.81) A4(12.7,1.27) A5(10.16,3.81) A6(7.62,1.27) A7(5.08,3.81) A8(2.54,1.27) A9(0,3.81) A10(-2.54,1.27) A11(-5.08,3.81) A12(-7.62,1.27) A13(-10.16,3.81) A14(-12.7,1.27) A15(-15.24,3.81) A16(-17.78,1.27) A17(-20.32,3.81) B1(20.32,-1.27) B2(17.78,-3.81) B3(15.24,-1.27) B4(12.7,-3.81) B5(10.16,-1.27) B6(7.62,-3.81) B7(5.08,-1.27) B8(2.54,-3.81) B9(0,-1.27) B10(-2.54,-3.81) B11(-5.08,-1.27) B12(-7.62,-3.81) B13(-10.16,-1.27) B14(-12.7,-3.81) B15(-15.24,-1.27) B16(-17.78,-3.81) B17(-20.32,-1.27)
PG_VG93K_F_G6D211
  round 1.778 hole 0.711: 01(20.32,1.27) 02(17.78,-1.27) 03(15.24,1.27) 04(12.7,-1.27) 05(10.16,1.27) 06(7.62,-1.27) 07(5.08,1.27) 08(2.54,-1.27) 09(0,1.27) 10(-2.54,-1.27) 11(-5.08,1.27) 12(-7.62,-1.27) 13(-10.16,1.27) 14(-12.7,-1.27) 15(-15.24,1.27) 16(-17.78,-1.27) 17(-20.32,1.27)
  rect 1.778x1.778 hole 0.711: A1(20.32,3.81) A2(17.78,1.27) A3(15.24,3.81) A4(12.7,1.27) A5(10.16,3.81) A6(7.62,1.27) A7(5.08,3.81) A8(2.54,1.27) A9(0,3.81) A10(-2.54,1.27) A11(-5.08,3.81) A12(-7.62,1.27) A13(-10.16,3.81) A14(-12.7,1.27) A15(-15.24,3.81) A16(-17.78,1.27) A17(-20.32,3.81) B1(20.32,-1.27) B2(17.78,-3.81) B3(15.24,-1.27) B4(12.7,-3.81) B5(10.16,-1.27) B6(7.62,-3.81) B7(5.08,-1.27) B8(2.54,-3.81) B9(0,-1.27) B10(-2.54,-3.81) B11(-5.08,-1.27) B12(-7.62,-3.81) B13(-10.16,-1.27) B14(-12.7,-3.81) B15(-15.24,-1.27) B16(-17.78,-3.81) B17(-20.32,-1.27)
PG_VG93K_F_G6D212
  round 1.778 hole 0.711: 01(20.32,1.27) 02(17.78,-1.27) 03(15.24,1.27) 04(12.7,-1.27) 05(10.16,1.27) 06(7.62,-1.27) 07(5.08,1.27) 08(2.54,-1.27) 09(0,1.27) 10(-2.54,-1.27) 11(-5.08,1.27) 12(-7.62,-1.27) 13(-10.16,1.27) 14(-12.7,-1.27) 15(-15.24,1.27) 16(-17.78,-1.27) 17(-20.32,1.27)
  rect 1.778x1.778 hole 0.711: A1(20.32,3.81) A2(17.78,1.27) A3(15.24,3.81) A4(12.7,1.27) A5(10.16,3.81) A6(7.62,1.27) A7(5.08,3.81) A8(2.54,1.27) A9(0,3.81) A10(-2.54,1.27) A11(-5.08,3.81) A12(-7.62,1.27) A13(-10.16,3.81) A14(-12.7,1.27) A15(-15.24,3.81) A16(-17.78,1.27) A17(-20.32,3.81) B1(20.32,-1.27) B2(17.78,-3.81) B3(15.24,-1.27) B4(12.7,-3.81) B5(10.16,-1.27) B6(7.62,-3.81) B7(5.08,-1.27) B8(2.54,-3.81) B9(0,-1.27) B10(-2.54,-3.81) B11(-5.08,-1.27) B12(-7.62,-3.81) B13(-10.16,-1.27) B14(-12.7,-3.81) B15(-15.24,-1.27) B16(-17.78,-3.81) B17(-20.32,-1.27)
PG_VG93K_F_G6D213
  round 1.778 hole 0.711: 01(20.32,1.27) 02(17.78,-1.27) 03(15.24,1.27) 04(12.7,-1.27) 05(10.16,1.27) 06(7.62,-1.27) 07(5.08,1.27) 08(2.54,-1.27) 09(0,1.27) 10(-2.54,-1.27) 11(-5.08,1.27) 12(-7.62,-1.27) 13(-10.16,1.27) 14(-12.7,-1.27) 15(-15.24,1.27) 16(-17.78,-1.27) 17(-20.32,1.27)
  rect 1.778x1.778 hole 0.711: A1(20.32,3.81) A2(17.78,1.27) A3(15.24,3.81) A4(12.7,1.27) A5(10.16,3.81) A6(7.62,1.27) A7(5.08,3.81) A8(2.54,1.27) A9(0,3.81) A10(-2.54,1.27) A11(-5.08,3.81) A12(-7.62,1.27) A13(-10.16,3.81) A14(-12.7,1.27) A15(-15.24,3.81) A16(-17.78,1.27) A17(-20.32,3.81) B1(20.32,-1.27) B2(17.78,-3.81) B3(15.24,-1.27) B4(12.7,-3.81) B5(10.16,-1.27) B6(7.62,-3.81) B7(5.08,-1.27) B8(2.54,-3.81) B9(0,-1.27) B10(-2.54,-3.81) B11(-5.08,-1.27) B12(-7.62,-3.81) B13(-10.16,-1.27) B14(-12.7,-3.81) B15(-15.24,-1.27) B16(-17.78,-3.81) B17(-20.32,-1.27)
PG_VG93K_F_G6D214
  round 1.778 hole 0.711: 01(20.32,1.27) 02(17.78,-1.27) 03(15.24,1.27) 04(12.7,-1.27) 05(10.16,1.27) 06(7.62,-1.27) 07(5.08,1.27) 08(2.54,-1.27) 09(0,1.27) 10(-2.54,-1.27) 11(-5.08,1.27) 12(-7.62,-1.27) 13(-10.16,1.27) 14(-12.7,-1.27) 15(-15.24,1.27) 16(-17.78,-1.27) 17(-20.32,1.27)
  rect 1.778x1.778 hole 0.711: A1(20.32,3.81) A2(17.78,1.27) A3(15.24,3.81) A4(12.7,1.27) A5(10.16,3.81) A6(7.62,1.27) A7(5.08,3.81) A8(2.54,1.27) A9(0,3.81) A10(-2.54,1.27) A11(-5.08,3.81) A12(-7.62,1.27) A13(-10.16,3.81) A14(-12.7,1.27) A15(-15.24,3.81) A16(-17.78,1.27) A17(-20.32,3.81) B1(20.32,-1.27) B2(17.78,-3.81) B3(15.24,-1.27) B4(12.7,-3.81) B5(10.16,-1.27) B6(7.62,-3.81) B7(5.08,-1.27) B8(2.54,-3.81) B9(0,-1.27) B10(-2.54,-3.81) B11(-5.08,-1.27) B12(-7.62,-3.81) B13(-10.16,-1.27) B14(-12.7,-3.81) B15(-15.24,-1.27) B16(-17.78,-3.81) B17(-20.32,-1.27)
PG_VG93K_F_G6D215
  round 1.778 hole 0.711: 01(20.32,1.27) 02(17.78,-1.27) 03(15.24,1.27) 04(12.7,-1.27) 05(10.16,1.27) 06(7.62,-1.27) 07(5.08,1.27) 08(2.54,-1.27) 09(0,1.27) 10(-2.54,-1.27) 11(-5.08,1.27) 12(-7.62,-1.27) 13(-10.16,1.27) 14(-12.7,-1.27) 15(-15.24,1.27) 16(-17.78,-1.27) 17(-20.32,1.27)
  rect 1.778x1.778 hole 0.711: A1(20.32,3.81) A2(17.78,1.27) A3(15.24,3.81) A4(12.7,1.27) A5(10.16,3.81) A6(7.62,1.27) A7(5.08,3.81) A8(2.54,1.27) A9(0,3.81) A10(-2.54,1.27) A11(-5.08,3.81) A12(-7.62,1.27) A13(-10.16,3.81) A14(-12.7,1.27) A15(-15.24,3.81) A16(-17.78,1.27) A17(-20.32,3.81) B1(20.32,-1.27) B2(17.78,-3.81) B3(15.24,-1.27) B4(12.7,-3.81) B5(10.16,-1.27) B6(7.62,-3.81) B7(5.08,-1.27) B8(2.54,-3.81) B9(0,-1.27) B10(-2.54,-3.81) B11(-5.08,-1.27) B12(-7.62,-3.81) B13(-10.16,-1.27) B14(-12.7,-3.81) B15(-15.24,-1.27) B16(-17.78,-3.81) B17(-20.32,-1.27)
PG_VG93K_F_G6D216
  round 1.778 hole 0.711: 01(20.32,1.27) 02(17.78,-1.27) 03(15.24,1.27) 04(12.7,-1.27) 05(10.16,1.27) 06(7.62,-1.27) 07(5.08,1.27) 08(2.54,-1.27) 09(0,1.27) 10(-2.54,-1.27) 11(-5.08,1.27) 12(-7.62,-1.27) 13(-10.16,1.27) 14(-12.7,-1.27) 15(-15.24,1.27) 16(-17.78,-1.27) 17(-20.32,1.27)
  rect 1.778x1.778 hole 0.711: A1(20.32,3.81) A2(17.78,1.27) A3(15.24,3.81) A4(12.7,1.27) A5(10.16,3.81) A6(7.62,1.27) A7(5.08,3.81) A8(2.54,1.27) A9(0,3.81) A10(-2.54,1.27) A11(-5.08,3.81) A12(-7.62,1.27) A13(-10.16,3.81) A14(-12.7,1.27) A15(-15.24,3.81) A16(-17.78,1.27) A17(-20.32,3.81) B1(20.32,-1.27) B2(17.78,-3.81) B3(15.24,-1.27) B4(12.7,-3.81) B5(10.16,-1.27) B6(7.62,-3.81) B7(5.08,-1.27) B8(2.54,-3.81) B9(0,-1.27) B10(-2.54,-3.81) B11(-5.08,-1.27) B12(-7.62,-3.81) B13(-10.16,-1.27) B14(-12.7,-3.81) B15(-15.24,-1.27) B16(-17.78,-3.81) B17(-20.32,-1.27)
PG_VG93K_F_G6UTI7
  round 1.778 hole 0.711: A01(20.32,1.27) A02(17.78,1.27) A03(15.24,1.27) A04(12.7,1.27) A05(10.16,1.27) A06(7.62,1.27) A07(5.08,1.27) A08(2.54,1.27) A09(0,1.27) A10(-2.54,1.27) A11(-5.08,1.27) A12(-7.62,1.27) A13(-10.16,1.27) A14(-12.7,1.27) A15(-15.24,1.27) A16(-17.78,1.27) A17(-20.32,1.27) B01(20.32,-1.27) B02(17.78,-1.27) B03(15.24,-1.27) B04(12.7,-1.27) B05(10.16,-1.27) B06(7.62,-1.27) B07(5.08,-1.27) B08(2.54,-1.27) B09(0,-1.27) B10(-2.54,-1.27) B11(-5.08,-1.27) B12(-7.62,-1.27) B13(-10.16,-1.27) B14(-12.7,-1.27) B15(-15.24,-1.27) B16(-17.78,-1.27) B17(-20.32,-1.27)
PG_VG93K_F_G7D217
  round 1.778 hole 0.711: 01(20.32,1.27) 02(17.78,-1.27) 03(15.24,1.27) 04(12.7,-1.27) 05(10.16,1.27) 06(7.62,-1.27) 07(5.08,1.27) 08(2.54,-1.27) 09(0,1.27) 10(-2.54,-1.27) 11(-5.08,1.27) 12(-7.62,-1.27) 13(-10.16,1.27) 14(-12.7,-1.27) 15(-15.24,1.27) 16(-17.78,-1.27) 17(-20.32,1.27)
  rect 1.778x1.778 hole 0.711: A1(20.32,3.81) A2(17.78,1.27) A3(15.24,3.81) A4(12.7,1.27) A5(10.16,3.81) A6(7.62,1.27) A7(5.08,3.81) A8(2.54,1.27) A9(0,3.81) A10(-2.54,1.27) A11(-5.08,3.81) A12(-7.62,1.27) A13(-10.16,3.81) A14(-12.7,1.27) A15(-15.24,3.81) A16(-17.78,1.27) A17(-20.32,3.81) B1(20.32,-1.27) B2(17.78,-3.81) B3(15.24,-1.27) B4(12.7,-3.81) B5(10.16,-1.27) B6(7.62,-3.81) B7(5.08,-1.27) B8(2.54,-3.81) B9(0,-1.27) B10(-2.54,-3.81) B11(-5.08,-1.27) B12(-7.62,-3.81) B13(-10.16,-1.27) B14(-12.7,-3.81) B15(-15.24,-1.27) B16(-17.78,-3.81) B17(-20.32,-1.27)
PG_VG93K_F_G7D218
  round 1.778 hole 0.711: 01(20.32,1.27) 02(17.78,-1.27) 03(15.24,1.27) 04(12.7,-1.27) 05(10.16,1.27) 06(7.62,-1.27) 07(5.08,1.27) 08(2.54,-1.27) 09(0,1.27) 10(-2.54,-1.27) 11(-5.08,1.27) 12(-7.62,-1.27) 13(-10.16,1.27) 14(-12.7,-1.27) 15(-15.24,1.27) 16(-17.78,-1.27) 17(-20.32,1.27)
  rect 1.778x1.778 hole 0.711: A1(20.32,3.81) A2(17.78,1.27) A3(15.24,3.81) A4(12.7,1.27) A5(10.16,3.81) A6(7.62,1.27) A7(5.08,3.81) A8(2.54,1.27) A9(0,3.81) A10(-2.54,1.27) A11(-5.08,3.81) A12(-7.62,1.27) A13(-10.16,3.81) A14(-12.7,1.27) A15(-15.24,3.81) A16(-17.78,1.27) A17(-20.32,3.81) B1(20.32,-1.27) B2(17.78,-3.81) B3(15.24,-1.27) B4(12.7,-3.81) B5(10.16,-1.27) B6(7.62,-3.81) B7(5.08,-1.27) B8(2.54,-3.81) B9(0,-1.27) B10(-2.54,-3.81) B11(-5.08,-1.27) B12(-7.62,-3.81) B13(-10.16,-1.27) B14(-12.7,-3.81) B15(-15.24,-1.27) B16(-17.78,-3.81) B17(-20.32,-1.27)
PG_VG93K_F_G7D219
  round 1.778 hole 0.711: 01(20.32,1.27) 02(17.78,-1.27) 03(15.24,1.27) 04(12.7,-1.27) 05(10.16,1.27) 06(7.62,-1.27) 07(5.08,1.27) 08(2.54,-1.27) 09(0,1.27) 10(-2.54,-1.27) 11(-5.08,1.27) 12(-7.62,-1.27) 13(-10.16,1.27) 14(-12.7,-1.27) 15(-15.24,1.27) 16(-17.78,-1.27) 17(-20.32,1.27)
  rect 1.778x1.778 hole 0.711: A1(20.32,3.81) A2(17.78,1.27) A3(15.24,3.81) A4(12.7,1.27) A5(10.16,3.81) A6(7.62,1.27) A7(5.08,3.81) A8(2.54,1.27) A9(0,3.81) A10(-2.54,1.27) A11(-5.08,3.81) A12(-7.62,1.27) A13(-10.16,3.81) A14(-12.7,1.27) A15(-15.24,3.81) A16(-17.78,1.27) A17(-20.32,3.81) B1(20.32,-1.27) B2(17.78,-3.81) B3(15.24,-1.27) B4(12.7,-3.81) B5(10.16,-1.27) B6(7.62,-3.81) B7(5.08,-1.27) B8(2.54,-3.81) B9(0,-1.27) B10(-2.54,-3.81) B11(-5.08,-1.27) B12(-7.62,-3.81) B13(-10.16,-1.27) B14(-12.7,-3.81) B15(-15.24,-1.27) B16(-17.78,-3.81) B17(-20.32,-1.27)
PG_VG93K_F_G7D220
  round 1.778 hole 0.711: 01(20.32,1.27) 02(17.78,-1.27) 03(15.24,1.27) 04(12.7,-1.27) 05(10.16,1.27) 06(7.62,-1.27) 07(5.08,1.27) 08(2.54,-1.27) 09(0,1.27) 10(-2.54,-1.27) 11(-5.08,1.27) 12(-7.62,-1.27) 13(-10.16,1.27) 14(-12.7,-1.27) 15(-15.24,1.27) 16(-17.78,-1.27) 17(-20.32,1.27)
  rect 1.778x1.778 hole 0.711: A1(20.32,3.81) A2(17.78,1.27) A3(15.24,3.81) A4(12.7,1.27) A5(10.16,3.81) A6(7.62,1.27) A7(5.08,3.81) A8(2.54,1.27) A9(0,3.81) A10(-2.54,1.27) A11(-5.08,3.81) A12(-7.62,1.27) A13(-10.16,3.81) A14(-12.7,1.27) A15(-15.24,3.81) A16(-17.78,1.27) A17(-20.32,3.81) B1(20.32,-1.27) B2(17.78,-3.81) B3(15.24,-1.27) B4(12.7,-3.81) B5(10.16,-1.27) B6(7.62,-3.81) B7(5.08,-1.27) B8(2.54,-3.81) B9(0,-1.27) B10(-2.54,-3.81) B11(-5.08,-1.27) B12(-7.62,-3.81) B13(-10.16,-1.27) B14(-12.7,-3.81) B15(-15.24,-1.27) B16(-17.78,-3.81) B17(-20.32,-1.27)
PG_VG93K_F_G7D221
  round 1.778 hole 0.711: 01(20.32,1.27) 02(17.78,-1.27) 03(15.24,1.27) 04(12.7,-1.27) 05(10.16,1.27) 06(7.62,-1.27) 07(5.08,1.27) 08(2.54,-1.27) 09(0,1.27) 10(-2.54,-1.27) 11(-5.08,1.27) 12(-7.62,-1.27) 13(-10.16,1.27) 14(-12.7,-1.27) 15(-15.24,1.27) 16(-17.78,-1.27) 17(-20.32,1.27)
  rect 1.778x1.778 hole 0.711: A1(20.32,3.81) A2(17.78,1.27) A3(15.24,3.81) A4(12.7,1.27) A5(10.16,3.81) A6(7.62,1.27) A7(5.08,3.81) A8(2.54,1.27) A9(0,3.81) A10(-2.54,1.27) A11(-5.08,3.81) A12(-7.62,1.27) A13(-10.16,3.81) A14(-12.7,1.27) A15(-15.24,3.81) A16(-17.78,1.27) A17(-20.32,3.81) B1(20.32,-1.27) B2(17.78,-3.81) B3(15.24,-1.27) B4(12.7,-3.81) B5(10.16,-1.27) B6(7.62,-3.81) B7(5.08,-1.27) B8(2.54,-3.81) B9(0,-1.27) B10(-2.54,-3.81) B11(-5.08,-1.27) B12(-7.62,-3.81) B13(-10.16,-1.27) B14(-12.7,-3.81) B15(-15.24,-1.27) B16(-17.78,-3.81) B17(-20.32,-1.27)
PG_VG93K_F_G7D222
  round 1.778 hole 0.711: 01(20.32,1.27) 02(17.78,-1.27) 03(15.24,1.27) 04(12.7,-1.27) 05(10.16,1.27) 06(7.62,-1.27) 07(5.08,1.27) 08(2.54,-1.27) 09(0,1.27) 10(-2.54,-1.27) 11(-5.08,1.27) 12(-7.62,-1.27) 13(-10.16,1.27) 14(-12.7,-1.27) 15(-15.24,1.27) 16(-17.78,-1.27) 17(-20.32,1.27)
  rect 1.778x1.778 hole 0.711: A1(20.32,3.81) A2(17.78,1.27) A3(15.24,3.81) A4(12.7,1.27) A5(10.16,3.81) A6(7.62,1.27) A7(5.08,3.81) A8(2.54,1.27) A9(0,3.81) A10(-2.54,1.27) A11(-5.08,3.81) A12(-7.62,1.27) A13(-10.16,3.81) A14(-12.7,1.27) A15(-15.24,3.81) A16(-17.78,1.27) A17(-20.32,3.81) B1(20.32,-1.27) B2(17.78,-3.81) B3(15.24,-1.27) B4(12.7,-3.81) B5(10.16,-1.27) B6(7.62,-3.81) B7(5.08,-1.27) B8(2.54,-3.81) B9(0,-1.27) B10(-2.54,-3.81) B11(-5.08,-1.27) B12(-7.62,-3.81) B13(-10.16,-1.27) B14(-12.7,-3.81) B15(-15.24,-1.27) B16(-17.78,-3.81) B17(-20.32,-1.27)
PG_VG93K_F_G7D223
  round 1.778 hole 0.711: 01(20.32,1.27) 02(17.78,-1.27) 03(15.24,1.27) 04(12.7,-1.27) 05(10.16,1.27) 06(7.62,-1.27) 07(5.08,1.27) 08(2.54,-1.27) 09(0,1.27) 10(-2.54,-1.27) 11(-5.08,1.27) 12(-7.62,-1.27) 13(-10.16,1.27) 14(-12.7,-1.27) 15(-15.24,1.27) 16(-17.78,-1.27) 17(-20.32,1.27)
  rect 1.778x1.778 hole 0.711: A1(20.32,3.81) A2(17.78,1.27) A3(15.24,3.81) A4(12.7,1.27) A5(10.16,3.81) A6(7.62,1.27) A7(5.08,3.81) A8(2.54,1.27) A9(0,3.81) A10(-2.54,1.27) A11(-5.08,3.81) A12(-7.62,1.27) A13(-10.16,3.81) A14(-12.7,1.27) A15(-15.24,3.81) A16(-17.78,1.27) A17(-20.32,3.81) B1(20.32,-1.27) B2(17.78,-3.81) B3(15.24,-1.27) B4(12.7,-3.81) B5(10.16,-1.27) B6(7.62,-3.81) B7(5.08,-1.27) B8(2.54,-3.81) B9(0,-1.27) B10(-2.54,-3.81) B11(-5.08,-1.27) B12(-7.62,-3.81) B13(-10.16,-1.27) B14(-12.7,-3.81) B15(-15.24,-1.27) B16(-17.78,-3.81) B17(-20.32,-1.27)
PG_VG93K_F_G7D224
  round 1.778 hole 0.711: 01(20.32,1.27) 02(17.78,-1.27) 03(15.24,1.27) 04(12.7,-1.27) 05(10.16,1.27) 06(7.62,-1.27) 07(5.08,1.27) 08(2.54,-1.27) 09(0,1.27) 10(-2.54,-1.27) 11(-5.08,1.27) 12(-7.62,-1.27) 13(-10.16,1.27) 14(-12.7,-1.27) 15(-15.24,1.27) 16(-17.78,-1.27) 17(-20.32,1.27)
  rect 1.778x1.778 hole 0.711: A1(20.32,3.81) A2(17.78,1.27) A3(15.24,3.81) A4(12.7,1.27) A5(10.16,3.81) A6(7.62,1.27) A7(5.08,3.81) A8(2.54,1.27) A9(0,3.81) A10(-2.54,1.27) A11(-5.08,3.81) A12(-7.62,1.27) A13(-10.16,3.81) A14(-12.7,1.27) A15(-15.24,3.81) A16(-17.78,1.27) A17(-20.32,3.81) B1(20.32,-1.27) B2(17.78,-3.81) B3(15.24,-1.27) B4(12.7,-3.81) B5(10.16,-1.27) B6(7.62,-3.81) B7(5.08,-1.27) B8(2.54,-3.81) B9(0,-1.27) B10(-2.54,-3.81) B11(-5.08,-1.27) B12(-7.62,-3.81) B13(-10.16,-1.27) B14(-12.7,-3.81) B15(-15.24,-1.27) B16(-17.78,-3.81) B17(-20.32,-1.27)
PG_VG93K_F_G7UTI8
  round 1.778 hole 0.711: A01(20.32,1.27) A02(17.78,1.27) A03(15.24,1.27) A04(12.7,1.27) A05(10.16,1.27) A06(7.62,1.27) A07(5.08,1.27) A08(2.54,1.27) A09(0,1.27) A10(-2.54,1.27) A11(-5.08,1.27) A12(-7.62,1.27) A13(-10.16,1.27) A14(-12.7,1.27) A15(-15.24,1.27) A16(-17.78,1.27) A17(-20.32,1.27) B01(20.32,-1.27) B02(17.78,-1.27) B03(15.24,-1.27) B04(12.7,-1.27) B05(10.16,-1.27) B06(7.62,-1.27) B07(5.08,-1.27) B08(2.54,-1.27) B09(0,-1.27) B10(-2.54,-1.27) B11(-5.08,-1.27) B12(-7.62,-1.27) B13(-10.16,-1.27) B14(-12.7,-1.27) B15(-15.24,-1.27) B16(-17.78,-1.27) B17(-20.32,-1.27)
PG_VG93K_F_G8D231
  round 1.778 hole 0.711: 01(20.32,1.27) 02(17.78,-1.27) 03(15.24,1.27) 04(12.7,-1.27) 05(10.16,1.27) 06(7.62,-1.27) 07(5.08,1.27) 08(2.54,-1.27) 09(0,1.27) 10(-2.54,-1.27) 11(-5.08,1.27) 12(-7.62,-1.27) 13(-10.16,1.27) 14(-12.7,-1.27) 15(-15.24,1.27) 16(-17.78,-1.27) 17(-20.32,1.27)
  rect 1.778x1.778 hole 0.711: A1(20.32,3.81) A2(17.78,1.27) A3(15.24,3.81) A4(12.7,1.27) A5(10.16,3.81) A6(7.62,1.27) A7(5.08,3.81) A8(2.54,1.27) A9(0,3.81) A10(-2.54,1.27) A11(-5.08,3.81) A12(-7.62,1.27) A13(-10.16,3.81) A14(-12.7,1.27) A15(-15.24,3.81) A16(-17.78,1.27) A17(-20.32,3.81) B1(20.32,-1.27) B2(17.78,-3.81) B3(15.24,-1.27) B4(12.7,-3.81) B5(10.16,-1.27) B6(7.62,-3.81) B7(5.08,-1.27) B8(2.54,-3.81) B9(0,-1.27) B10(-2.54,-3.81) B11(-5.08,-1.27) B12(-7.62,-3.81) B13(-10.16,-1.27) B14(-12.7,-3.81) B15(-15.24,-1.27) B16(-17.78,-3.81) B17(-20.32,-1.27)
PG_VG93K_F_G8D431
  round 1.778 hole 0.711: 01(20.32,1.27) 02(17.78,-1.27) 03(15.24,1.27) 04(12.7,-1.27) 05(10.16,1.27) 06(7.62,-1.27) 07(5.08,1.27) 08(2.54,-1.27) 09(0,1.27) 10(-2.54,-1.27) 11(-5.08,1.27) 12(-7.62,-1.27) 13(-10.16,1.27) 14(-12.7,-1.27) 15(-15.24,1.27) 16(-17.78,-1.27) 17(-20.32,1.27)
  rect 1.778x1.778 hole 0.711: A1(20.32,3.81) A2(17.78,1.27) A3(15.24,3.81) A4(12.7,1.27) A5(10.16,3.81) A6(7.62,1.27) A7(5.08,3.81) A8(2.54,1.27) A9(0,3.81) A10(-2.54,1.27) A11(-5.08,3.81) A12(-7.62,1.27) A13(-10.16,3.81) A14(-12.7,1.27) A15(-15.24,3.81) A16(-17.78,1.27) A17(-20.32,3.81) B1(20.32,-1.27) B2(17.78,-3.81) B3(15.24,-1.27) B4(12.7,-3.81) B5(10.16,-1.27) B6(7.62,-3.81) B7(5.08,-1.27) B8(2.54,-3.81) B9(0,-1.27) B10(-2.54,-3.81) B11(-5.08,-1.27) B12(-7.62,-3.81) B13(-10.16,-1.27) B14(-12.7,-3.81) B15(-15.24,-1.27) B16(-17.78,-3.81) B17(-20.32,-1.27)
PG_VG93K_F_G8DPS8
  round 1.778 hole 0.711: A01(20.32,2.54) A02(17.78,2.54) A03(15.24,2.54) A04(12.7,2.54) A05(10.16,2.54) A06(7.62,2.54) A07(5.08,2.54) A08(2.54,2.54) A09(0,2.54) A10(-2.54,2.54) A11(-5.08,2.54) A12(-7.62,2.54) A13(-10.16,2.54) A14(-12.7,2.54) A15(-15.24,2.54) A16(-17.78,2.54) A17(-20.32,2.54) B01(20.32,0) B02(17.78,0) B03(15.24,0) B04(12.7,0) B05(10.16,0) B06(7.62,0) B07(5.08,0) B08(2.54,0) B09(0,0) B10(-2.54,0) B11(-5.08,0) B12(-7.62,0) B13(-10.16,0) B14(-12.7,0) B15(-15.24,0) B16(-17.78,0) B17(-20.32,0) C01(20.32,-2.54) C02(17.78,-2.54) C03(15.24,-2.54) C04(12.7,-2.54) C05(10.16,-2.54) C06(7.62,-2.54) C07(5.08,-2.54) C08(2.54,-2.54) C09(0,-2.54) C10(-2.54,-2.54) C11(-5.08,-2.54) C12(-7.62,-2.54) C13(-10.16,-2.54) C14(-12.7,-2.54) C15(-15.24,-2.54) C16(-17.78,-2.54) C17(-20.32,-2.54)
PG_VG93K_F_G8UTI4
  round 1.778 hole 0.711: A01(20.32,1.27) A02(17.78,1.27) A03(15.24,1.27) A04(12.7,1.27) A05(10.16,1.27) A06(7.62,1.27) A07(5.08,1.27) A08(2.54,1.27) A09(0,1.27) A10(-2.54,1.27) A11(-5.08,1.27) A12(-7.62,1.27) A13(-10.16,1.27) A14(-12.7,1.27) A15(-15.24,1.27) A16(-17.78,1.27) A17(-20.32,1.27) B01(20.32,-1.27) B02(17.78,-1.27) B03(15.24,-1.27) B04(12.7,-1.27) B05(10.16,-1.27) B06(7.62,-1.27) B07(5.08,-1.27) B08(2.54,-1.27) B09(0,-1.27) B10(-2.54,-1.27) B11(-5.08,-1.27) B12(-7.62,-1.27) B13(-10.16,-1.27) B14(-12.7,-1.27) B15(-15.24,-1.27) B16(-17.78,-1.27) B17(-20.32,-1.27)
PG_VG93K_F_HSM_G1D101_501_ND
  rect 1.626x1.626 smd: A1(-20.32,-3.81) A3(-15.24,-3.81) A5(-10.16,-3.81) A7(-5.08,-3.81) A9(0,-3.81) A11(5.08,-3.81) A13(10.16,-3.81) A15(15.24,-3.81) A17(20.32,-3.81) B2(-17.78,-1.27) B4(-12.7,-1.27) B6(-7.62,-1.27) B8(-2.54,-1.27) B10(2.54,-1.27) B12(7.62,-1.27) B14(12.7,-1.27) B16(17.78,-1.27) C1(-20.32,1.27) C3(-15.24,1.27) C5(-10.16,1.27) C7(-5.08,1.27) C9(0,1.27) C11(5.08,1.27) C13(10.16,1.27) C15(15.24,1.27) C17(20.32,1.27) D2(-17.78,3.81) D4(-12.7,3.81) D6(-7.62,3.81) D8(-2.54,3.81) D10(2.54,3.81) D12(7.62,3.81) D14(12.7,3.81) D16(17.78,3.81)
  round 1.626 smd: A2(-17.78,-3.81) A4(-12.7,-3.81) A6(-7.62,-3.81) A8(-2.54,-3.81) A10(2.54,-3.81) A12(7.62,-3.81) A14(12.7,-3.81) A16(17.78,-3.81) B1(-20.32,-1.27) B3(-15.24,-1.27) B5(-10.16,-1.27) B7(-5.08,-1.27) B9(0,-1.27) B11(5.08,-1.27) B13(10.16,-1.27) B15(15.24,-1.27) B17(20.32,-1.27) C2(-17.78,1.27) C4(-12.7,1.27) C6(-7.62,1.27) C8(-2.54,1.27) C10(2.54,1.27) C12(7.62,1.27) C14(12.7,1.27) C16(17.78,1.27) D3(-15.24,3.81) D5(-10.16,3.81) D7(-5.08,3.81) D9(0,3.81) D11(5.08,3.81) D13(10.16,3.81) D15(15.24,3.81)
PG_VG93K_F_HSM_G1D102_502_ND
  rect 1.626x1.626 smd: A1(-20.32,-3.81) A3(-15.24,-3.81) A5(-10.16,-3.81) A7(-5.08,-3.81) A9(0,-3.81) A11(5.08,-3.81) A13(10.16,-3.81) A15(15.24,-3.81) A17(20.32,-3.81) B2(-17.78,-1.27) B4(-12.7,-1.27) B6(-7.62,-1.27) B8(-2.54,-1.27) B10(2.54,-1.27) B12(7.62,-1.27) B14(12.7,-1.27) B16(17.78,-1.27) C1(-20.32,1.27) C3(-15.24,1.27) C5(-10.16,1.27) C7(-5.08,1.27) C9(0,1.27) C11(5.08,1.27) C13(10.16,1.27) C15(15.24,1.27) C17(20.32,1.27) D2(-17.78,3.81) D4(-12.7,3.81) D6(-7.62,3.81) D8(-2.54,3.81) D10(2.54,3.81) D12(7.62,3.81) D14(12.7,3.81) D16(17.78,3.81)
  round 1.626 smd: A2(-17.78,-3.81) A4(-12.7,-3.81) A6(-7.62,-3.81) A8(-2.54,-3.81) A10(2.54,-3.81) A12(7.62,-3.81) A14(12.7,-3.81) A16(17.78,-3.81) B1(-20.32,-1.27) B3(-15.24,-1.27) B5(-10.16,-1.27) B7(-5.08,-1.27) B9(0,-1.27) B11(5.08,-1.27) B13(10.16,-1.27) B15(15.24,-1.27) B17(20.32,-1.27) C2(-17.78,1.27) C4(-12.7,1.27) C6(-7.62,1.27) C8(-2.54,1.27) C10(2.54,1.27) C12(7.62,1.27) C14(12.7,1.27) C16(17.78,1.27) D3(-15.24,3.81) D5(-10.16,3.81) D7(-5.08,3.81) D9(0,3.81) D11(5.08,3.81) D13(10.16,3.81) D15(15.24,3.81)
PG_VG93K_F_HSM_G1D103_503_ND
  rect 1.626x1.626 smd: A1(-20.32,-3.81) A3(-15.24,-3.81) A5(-10.16,-3.81) A7(-5.08,-3.81) A9(0,-3.81) A11(5.08,-3.81) A13(10.16,-3.81) A15(15.24,-3.81) A17(20.32,-3.81) B2(-17.78,-1.27) B4(-12.7,-1.27) B6(-7.62,-1.27) B8(-2.54,-1.27) B10(2.54,-1.27) B12(7.62,-1.27) B14(12.7,-1.27) B16(17.78,-1.27) C1(-20.32,1.27) C3(-15.24,1.27) C5(-10.16,1.27) C7(-5.08,1.27) C9(0,1.27) C11(5.08,1.27) C13(10.16,1.27) C15(15.24,1.27) C17(20.32,1.27) D2(-17.78,3.81) D4(-12.7,3.81) D6(-7.62,3.81) D8(-2.54,3.81) D10(2.54,3.81) D12(7.62,3.81) D14(12.7,3.81) D16(17.78,3.81)
  round 1.626 smd: A2(-17.78,-3.81) A4(-12.7,-3.81) A6(-7.62,-3.81) A8(-2.54,-3.81) A10(2.54,-3.81) A12(7.62,-3.81) A14(12.7,-3.81) A16(17.78,-3.81) B1(-20.32,-1.27) B3(-15.24,-1.27) B5(-10.16,-1.27) B7(-5.08,-1.27) B9(0,-1.27) B11(5.08,-1.27) B13(10.16,-1.27) B15(15.24,-1.27) B17(20.32,-1.27) C2(-17.78,1.27) C4(-12.7,1.27) C6(-7.62,1.27) C8(-2.54,1.27) C10(2.54,1.27) C12(7.62,1.27) C14(12.7,1.27) C16(17.78,1.27) D3(-15.24,3.81) D5(-10.16,3.81) D7(-5.08,3.81) D9(0,3.81) D11(5.08,3.81) D13(10.16,3.81) D15(15.24,3.81)
